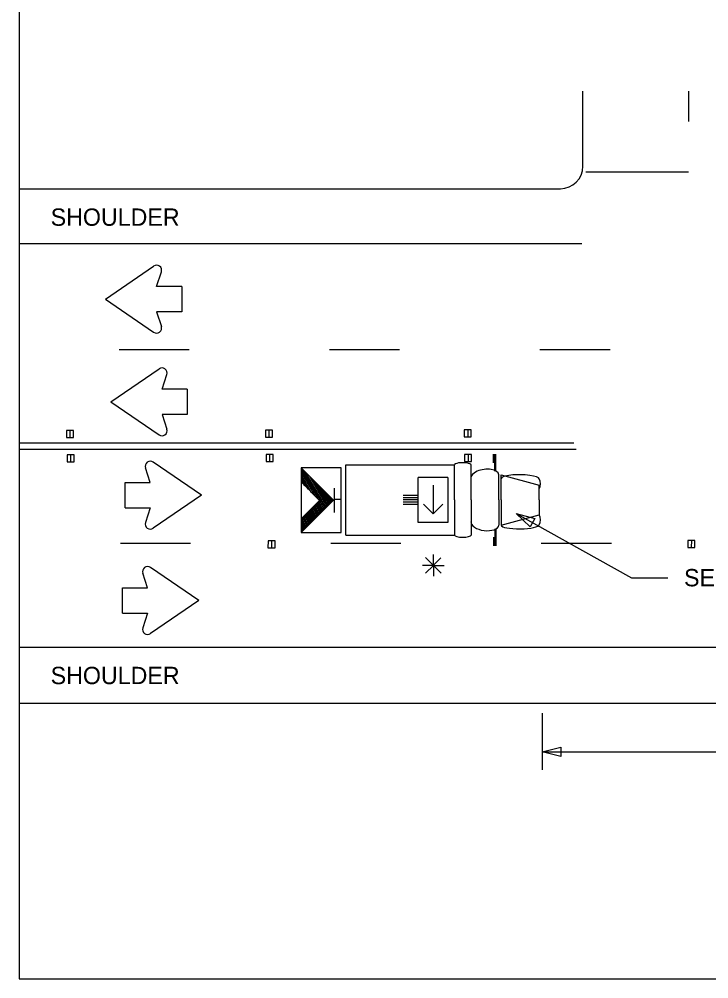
# Model space of a CAD drawing. Extents: x 1806907 to 1812607, y 675071 to 676228.
# Drawn here: x 1810956.7 to 1811195.1, y 675071.2 to 675403.2 of the extents above; entities that cross this region are included whole.
import ezdxf

# ---------------------------------------------------------------- set-up
doc = ezdxf.new("R2010")
doc.units = 0
for name, color, linetype in [('DSN_DRFT_Named-Boundary', 7, 'Continuous'), ('Level 1', 7, 'Continuous'), ('Working Level 1', 7, 'Continuous')]:
    doc.layers.add(name, color=color, linetype=linetype)

msp = doc.modelspace()

# ---------------------------------------------------------------- linework, layer by layer
at = {"layer": 'DSN_DRFT_Named-Boundary'}
msp.add_lwpolyline([(1810956.68, 675071.2), (1812606.68, 675071.2), (1812606.68, 676121.2), (1810956.68, 676121.2)], close=True, dxfattribs=at)
at = {"layer": 'Level 1'}
msp.add_lwpolyline([(1811128.53, 675232.23), (1811168.37, 675209.93), (1811180.91, 675209.93)], dxfattribs=at)
at = {"layer": 'Working Level 1'}
for p, q in [((1811151.58, 675352.35), (1811151.58, 675378.34)), ((1811152.65, 675350.48), (1811188.11, 675350.48)), ((1810956.68, 675344.59), (1811143.82, 675344.59)), ((1810956.68, 675325.65), (1811151.25, 675325.65)), ((1810986.49, 675306.39), (1811003.16, 675317.83)), ((1811004.21, 675310.76), (1811005.84, 675315.83)), ((1811012.89, 675310.76), (1811004.21, 675310.76)), ((1811012.89, 675310.76), (1811012.89, 675302.03)), ((1810986.49, 675306.39), (1811003.16, 675294.96)), ((1811012.89, 675302.03), (1811004.21, 675302.03)), ((1811004.21, 675302.03), (1811005.84, 675296.96)), ((1810988.36, 675270.81), (1811005.03, 675282.25)), ((1811006.08, 675275.18), (1811007.71, 675280.25)), ((1811014.76, 675275.18), (1811006.08, 675275.18)), ((1811014.76, 675275.18), (1811014.76, 675266.45)), ((1810988.36, 675270.81), (1811005.03, 675259.38)), ((1811014.76, 675266.45), (1811006.08, 675266.45)), ((1811006.08, 675266.45), (1811007.71, 675261.37)), ((1810975.45, 675260.93), (1810973.02, 675260.93)), ((1810973.02, 675260.93), (1810973.02, 675258.5)), ((1810974.24, 675260.93), (1810974.23, 675258.5)), ((1810975.45, 675258.5), (1810975.45, 675260.93)), ((1811041.83, 675261.04), (1811041.82, 675258.61)), ((1811044.25, 675261.04), (1811041.83, 675261.04)), ((1811043.05, 675261.04), (1811043.04, 675258.61)), ((1811044.25, 675258.61), (1811044.25, 675261.04)), ((1811113, 675261.15), (1811110.57, 675261.15)), ((1811110.57, 675261.15), (1811110.57, 675258.72)), ((1811111.79, 675261.15), (1811111.79, 675258.72)), ((1811113, 675258.72), (1811113, 675261.15)), ((1810956.68, 675256.63), (1811148.48, 675256.63)), ((1810973.02, 675258.5), (1810975.45, 675258.5)), ((1811041.82, 675258.61), (1811044.25, 675258.61)), ((1811110.57, 675258.72), (1811113, 675258.72)), ((1810956.68, 675254.52), (1811149.28, 675254.52)), ((1810973.23, 675252.56), (1810973.22, 675250.13)), ((1810973.22, 675250.13), (1810975.65, 675250.13)), ((1810975.65, 675252.56), (1810973.23, 675252.56)), ((1810974.44, 675252.56), (1810974.44, 675250.13)), ((1810975.65, 675250.13), (1810975.65, 675252.56)), ((1811019.69, 675238.53), (1811003.02, 675249.97)), ((1811044.46, 675252.67), (1811042.03, 675252.67)), ((1811042.03, 675252.67), (1811042.03, 675250.24)), ((1811042.03, 675250.24), (1811044.46, 675250.24)), ((1811043.25, 675252.67), (1811043.24, 675250.24)), ((1811044.46, 675250.24), (1811044.46, 675252.67)), ((1811113.08, 675252.67), (1811110.65, 675252.67)), ((1811110.65, 675252.67), (1811110.65, 675250.24)), ((1811110.65, 675250.24), (1811113.08, 675250.24)), ((1811111.87, 675252.67), (1811111.86, 675250.24)), ((1811113.08, 675250.24), (1811113.08, 675252.67)), ((1811120.65, 675249.74), (1811120.65, 675252.71)), ((1811121.12, 675246.88), (1811121.12, 675252.71)), ((1811121.52, 675246.88), (1811121.52, 675252.71)), ((1811001.96, 675242.9), (1811000.33, 675247.97)), ((1811054.12, 675247.97), (1811065.3, 675236.8)), ((1811069.6, 675249.01), (1811107.14, 675249.01)), ((1811069.6, 675224.76), (1811069.6, 675249.01)), ((1811107.14, 675236.89), (1811107.14, 675249.01)), ((1811112.9, 675236.89), (1811112.9, 675249.01)), ((1811054.12, 675243.12), (1811060.53, 675236.74)), ((1811104.94, 675244.65), (1811094.68, 675244.65)), ((1811094.68, 675229.12), (1811094.68, 675244.65)), ((1811104.94, 675244.65), (1811104.94, 675229.12)), ((1811122.53, 675236.89), (1811122.53, 675245.62)), ((1811123.33, 675245.62), (1811136.46, 675242.03)), ((1811123.33, 675236.89), (1811123.33, 675245.62)), ((1810993.29, 675234.17), (1810993.29, 675242.9)), ((1810993.29, 675242.9), (1811001.96, 675242.9)), ((1811065.68, 675232.6), (1811065.68, 675241.01)), ((1811099.81, 675242.01), (1811099.81, 675232.08)), ((1811136.46, 675236.89), (1811136.46, 675242.03)), ((1811019.69, 675238.53), (1811003.02, 675227.09)), ((1811054.12, 675230.34), (1811060.53, 675236.74)), ((1811054.18, 675225.68), (1811065.3, 675236.8)), ((1811068.01, 675237), (1811065.61, 675237)), ((1811094.68, 675238.43), (1811089.45, 675238.43)), ((1811094.68, 675237.66), (1811089.45, 675237.66)), ((1811094.68, 675236.88), (1811089.45, 675236.88)), ((1811107.14, 675236.89), (1811107.14, 675224.76)), ((1811112.9, 675236.89), (1811112.9, 675224.76)), ((1811122.53, 675236.89), (1811122.53, 675228.15)), ((1811123.33, 675236.89), (1811123.33, 675228.15)), ((1811136.46, 675236.89), (1811136.46, 675231.74)), ((1810993.29, 675234.17), (1811001.96, 675234.17)), ((1811001.96, 675234.17), (1811000.33, 675229.09)), ((1811094.68, 675236.11), (1811089.45, 675236.11)), ((1811094.68, 675235.33), (1811089.45, 675235.33)), ((1811099.81, 675232.08), (1811096.43, 675235.46)), ((1811099.81, 675232.08), (1811103.1, 675235.38)), ((1811123.33, 675228.15), (1811136.46, 675231.74)), ((1811104.94, 675229.12), (1811094.68, 675229.12)), ((1811121.12, 675226.89), (1811121.12, 675221.06)), ((1811121.52, 675226.89), (1811121.52, 675221.06)), ((1811069.6, 675224.76), (1811107.14, 675224.76)), ((1811120.65, 675224.03), (1811120.65, 675221.06)), ((1811042.71, 675222.77), (1811042.7, 675220.34)), ((1811042.7, 675220.34), (1811045.13, 675220.34)), ((1811045.13, 675222.77), (1811042.71, 675222.77)), ((1811043.92, 675222.77), (1811043.92, 675220.34)), ((1811045.13, 675220.34), (1811045.13, 675222.77)), ((1811190.29, 675222.88), (1811187.86, 675222.88)), ((1811187.86, 675222.88), (1811187.86, 675220.45)), ((1811187.86, 675220.45), (1811190.29, 675220.45)), ((1811189.08, 675222.88), (1811189.07, 675220.45)), ((1811190.29, 675220.45), (1811190.29, 675222.88)), ((1811099.88, 675214.27), (1811097.22, 675216.93)), ((1811099.81, 675214.22), (1811102.48, 675216.88)), ((1811099.88, 675214.27), (1811099.88, 675218.04)), ((1811018.76, 675202.08), (1811002.09, 675213.52)), ((1811099.88, 675214.27), (1811096.11, 675214.27)), ((1811099.88, 675214.27), (1811097.22, 675211.61)), ((1811099.88, 675214.27), (1811102.54, 675211.61)), ((1811099.88, 675214.27), (1811099.88, 675210.51)), ((1811099.88, 675214.27), (1811103.64, 675214.27)), ((1811001.04, 675206.44), (1810999.41, 675211.52)), ((1810992.36, 675197.71), (1810992.36, 675206.44)), ((1810992.36, 675206.44), (1811001.04, 675206.44)), ((1811018.76, 675202.08), (1811002.09, 675190.64)), ((1810992.36, 675197.71), (1811001.04, 675197.71)), ((1811001.04, 675197.71), (1810999.41, 675192.64)), ((1810956.68, 675185.99), (1811756.74, 675185.99)), ((1810956.68, 675166.6), (1811756.74, 675166.6)), ((1811137.45, 675163.13), (1811137.45, 675143.46)), ((1811137.45, 675149.72), (1811454.42, 675149.72)), ((1811137.45, 675149.72), (1811142.88, 675149.72))]:
    msp.add_line(p, q, dxfattribs=at)
for points in [[(1811188.07, 675378.34), (1811188.07, 675367.87)], [(1810991.22, 675288.91), (1811015.47, 675288.91)], [(1811063.97, 675288.91), (1811088.23, 675288.91)], [(1811136.73, 675288.91), (1811160.98, 675288.91)], [(1811054.12, 675247.45), (1811060.02, 675237.23)], [(1811054.12, 675246.58), (1811058.85, 675238.37)], [(1811054.62, 675247.48), (1811062.43, 675233.94)], [(1811055.81, 675246.28), (1811062.75, 675234.26)], [(1811054.12, 675245.69), (1811057.68, 675239.52)], [(1811054.12, 675244.82), (1811056.51, 675240.67)], [(1811054.12, 675243.93), (1811055.35, 675241.81)], [(1811054.12, 675243.05), (1811054.18, 675242.96)], [(1811057.01, 675245.09), (1811063.08, 675234.59)], [(1811058.21, 675243.88), (1811063.4, 675234.9)], [(1811059.41, 675242.69), (1811063.72, 675235.23)], [(1811060.61, 675241.48), (1811064.05, 675235.53)], [(1811061.81, 675240.29), (1811064.38, 675235.83)], [(1811060.06, 675236.28), (1811061.79, 675233.3)], [(1811060.39, 675236.6), (1811062.11, 675233.62)], [(1811063.01, 675239.1), (1811064.68, 675236.2)], [(1811064.11, 675238.01), (1811064.98, 675236.51)], [(1811056.85, 675233.06), (1811058.56, 675230.09)], [(1811057.17, 675233.39), (1811058.89, 675230.42)], [(1811057.49, 675233.71), (1811059.21, 675230.74)], [(1811057.8, 675234.03), (1811059.53, 675231.06)], [(1811058.13, 675234.35), (1811059.86, 675231.37)], [(1811058.45, 675234.67), (1811060.17, 675231.7)], [(1811058.77, 675234.99), (1811060.5, 675232.02)], [(1811059.1, 675235.32), (1811060.82, 675232.34)], [(1811059.42, 675235.64), (1811061.14, 675232.66)], [(1811059.74, 675235.95), (1811061.46, 675232.98)], [(1811054.12, 675229.87), (1811055.66, 675227.21)], [(1811054.27, 675230.49), (1811055.98, 675227.53)], [(1811054.59, 675230.82), (1811056.31, 675227.85)], [(1811054.91, 675231.13), (1811056.62, 675228.17)], [(1811055.24, 675231.46), (1811056.95, 675228.49)], [(1811055.55, 675231.78), (1811057.27, 675228.82)], [(1811055.88, 675232.1), (1811057.59, 675229.13)], [(1811056.2, 675232.42), (1811057.92, 675229.45)], [(1811056.52, 675232.74), (1811058.24, 675229.77)], [(1811054.12, 675228.99), (1811055.34, 675226.88)], [(1811054.12, 675228.11), (1811055.02, 675226.56)], [(1811054.12, 675227.23), (1811054.7, 675226.24)], [(1811054.12, 675226.35), (1811054.37, 675225.93)], [(1810991.66, 675221.92), (1811015.91, 675221.92)], [(1811064.41, 675221.92), (1811088.67, 675221.92)], [(1811137.17, 675221.92), (1811161.42, 675221.92)]]:
    msp.add_lwpolyline(points, dxfattribs=at)
for points in [[(1811054.12, 675247.97), (1811054.12, 675225.67), (1811068.06, 675225.67), (1811068.06, 675247.97)], [(1811133.41, 675227.64), (1811128.53, 675232.23), (1811135, 675230.47)], [(1811143.95, 675148.1), (1811137.45, 675149.72), (1811143.95, 675151.35)]]:
    msp.add_lwpolyline(points, close=True, dxfattribs=at)
for centre, radius, start, end in [((1811143.82, 675352.35), 7.76, 270, 360), ((1811004.16, 675316.37), 1.77, 342.1824, 124.4455), ((1811004.16, 675296.42), 1.77, 235.5545, 17.8176), ((1811006.03, 675280.79), 1.77, 342.1824, 124.4455), ((1811006.03, 675260.84), 1.77, 235.5545, 17.8176), ((1811002.02, 675248.51), 1.77, 55.5545, 197.8176), ((1811133.25, 675242.47), 3.64, 331.8801, 28.1199), ((1811133.25, 675230.02), 3.64, 331.8801, 28.1199), ((1811002.02, 675228.55), 1.77, 162.1824, 304.4455), ((1811001.09, 675212.06), 1.77, 55.5545, 197.8176), ((1811001.09, 675192.1), 1.77, 162.1824, 304.4455)]:
    msp.add_arc(centre, radius, start, end, dxfattribs=at)
for centre, major_axis, ratio, start_param, end_param in [((1811110.02, 675249.01), (2.88, 0), 0.269913, 0, 3.141593), ((1811117.71, 675245.02), (4.82, 0.6), 0.503092, 0, 3.141593), ((1811129.9, 675244.27), (6.56, -0.08), 0.2034, 0, 3.141593), ((1811117.71, 675228.75), (4.82, -0.6), 0.503092, 3.141593, 6.283185), ((1811129.9, 675228.23), (6.56, 0.08), 0.2034, 3.141593, 6.283185), ((1811110.02, 675224.76), (2.88, 0), 0.269913, 3.141593, 6.283185)]:
    msp.add_ellipse(centre, major_axis=major_axis, ratio=ratio, start_param=start_param, end_param=end_param, dxfattribs=at)

# ---------------------------------------------------------------- texts
for p in [(1810967.56, 675331.76), (1810967.56, 675173.16)]:
    msp.add_text('SHOULDER', height=6, rotation=0, dxfattribs=at).set_placement(p)
msp.add_text('SEE TRAIL/SHADOW VEHICLE A', height=6, dxfattribs=at).set_placement((1811186.55, 675207))

doc.saveas('drawing.dxf')
